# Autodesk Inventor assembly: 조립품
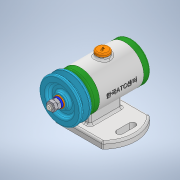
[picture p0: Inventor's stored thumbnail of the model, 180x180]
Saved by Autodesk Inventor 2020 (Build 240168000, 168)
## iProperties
Created: 2021-09
Part Number: 조립품
Document SubType Name: Assembly
Designer: Administrator
Author: Administrator
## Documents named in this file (14)
- C:\Users\Administrator\Desktop\710906V1021\조립품.iam
- C:\Users\Administrator\Desktop\710906V1021\본체.ipt
- C:\Users\Administrator\Desktop\710906V1021\캡.ipt
- C:\Users\Administrator\Desktop\710906V1021\너트 M8.ipt
- C:\Users\Administrator\Desktop\710906V1021\스프링와셔 8.ipt
- C:\Users\Administrator\Desktop\710906V1021\와셔 8x17.ipt
- C:\Users\Administrator\Desktop\710906V1021\볼트 M4x12.ipt
- C:\Users\Administrator\Desktop\710906V1021\V벨트풀리.ipt
- C:\Users\Administrator\Desktop\710906V1021\키 3x3.ipt
- C:\Users\Administrator\Desktop\710906V1021\베어링 15x32x9.ipt
- C:\Users\Administrator\Desktop\710906V1021\오일 실 15x25x7.ipt
- C:\Users\Administrator\Desktop\710906V1021\뒤커버.ipt
- C:\Users\Administrator\Desktop\710906V1021\앞커버.ipt
- C:\Users\Administrator\Desktop\710906V1021\축.ipt
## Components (1 placed, 1 different names)
1. V벨트풀리:1
